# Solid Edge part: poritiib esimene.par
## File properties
Title: poritiib esimene
Author: Stella-Marii
Template: Iso Metric Part.par
Last saved by: Stella-Marii
Revision: 6
Application: Solid Edge
Document Number: 32
Density: 1024,000 kg/m^3
Accuracy: 0,990
Username: Stella-Marii
Material: ABS Plastic, high impact
Face Style: Red
Fill Style: ANSI34(Plastic)
Virtual Style: Red (Shiny)
Grouping: Non-metals\Plastics
LibraryName: Materials
Coef. of Thermal Exp: 9e-05
Thermal Conductivity: 0.2
Specific Heat: 0.0
Modulus of Elasticity: 1378951400.0
Poisson's Ratio: 0.4
Yield Stress: 31026406.5
Ultimate Stress: 0.0
Elongation: 0.0
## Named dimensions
RefPlane_5: Distance = 65.4449 mm
BlueSurf_5: StartTangentMagnitude1 = 1; StartTangentMagnitude2 = 1; StartTangentMagnitude3 = 1; EndTangentMagnitude1 = 1; EndTangentMagnitude2 = 1; EndTangentMagnitude3 = 1
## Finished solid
Body 1: sheet body, 1 face, 4 edges, 4 vertices.
  Faces by surface: spline 1
  Edges by curve: circle 2, spline 2
Bounding box of the edges (mm; curved faces can reach further): 230.000 x 80.000 x 87.306, from (0, -40, -65.4449) to (230, 40, 21.8614).
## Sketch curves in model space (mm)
arc centre (42.5, 0, -65.4449) radius 42.5 from (28.1386, 40, -65.4449) through (0.019, -1.2708, -65.4449) to (28.1386, -40, -65.4449)
arc centre (187.5, 0, -65.4449) radius 42.5 from (201.8614, 40, -65.4449) through (229.981, -1.2708, -65.4449) to (201.8614, -40, -65.4449)
arc centre (115, 0, 7.5) radius 42.5 from (115, -40, 21.8614) through (115, 1.2708, 49.981) to (115, 40, 21.8614)
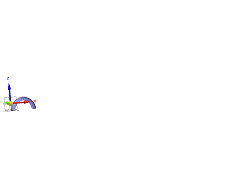
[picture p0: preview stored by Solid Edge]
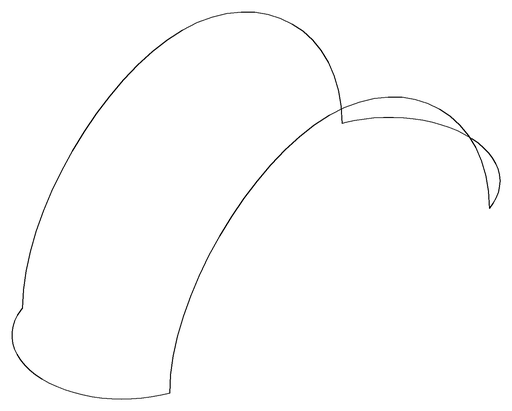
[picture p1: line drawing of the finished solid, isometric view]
